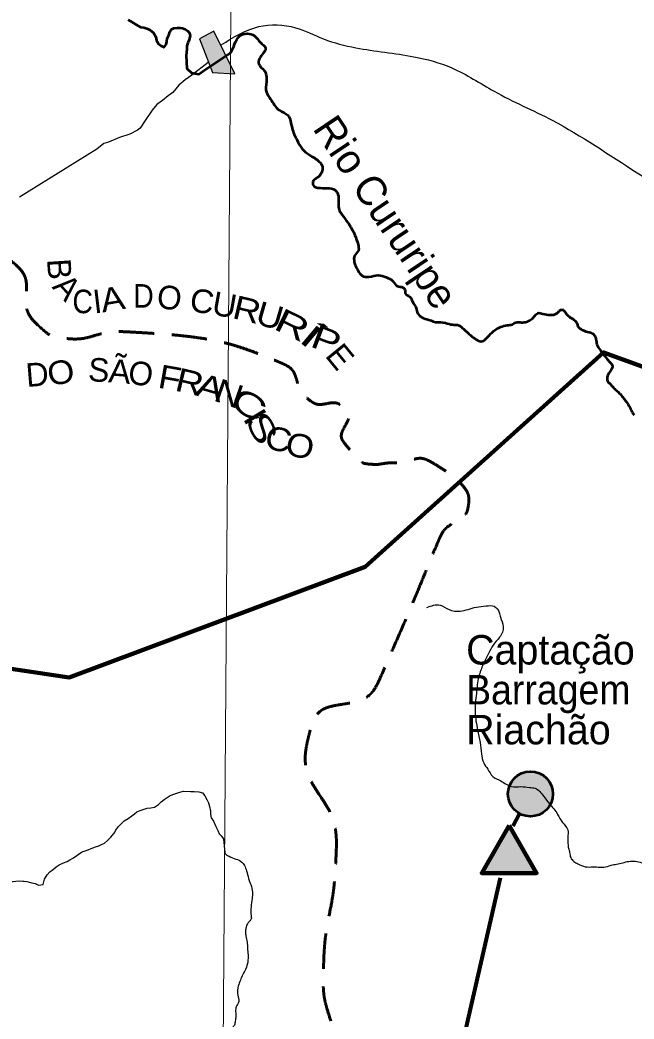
# Model space of a CAD drawing. Extents: x 553962 to 842807, y 8883888 to 9032388.
# Drawn here: x 770713 to 781131, y 8905842 to 8922804 of the extents above; entities that cross this region are included whole.
import ezdxf
from ezdxf.enums import TextEntityAlignment as Align

# ---------------------------------------------------------------- set-up
doc = ezdxf.new("R2010")
doc.units = 0
doc.header["$LTSCALE"] = 200
doc.linetypes.add('MEDIUM_DASHED', pattern=[4.5, 3, -1.5])
for name, color, linetype, lineweight in [('1', 7, 'Continuous', 13), ('10', 7, 'MEDIUM_DASHED', 60), ('12', 7, 'Continuous', 25), ('21', 7, 'Continuous', 25), ('24', 7, 'Continuous', 25), ('28', 7, 'Continuous', 40), ('41', 7, 'Continuous', 40), ('57', 7, 'Continuous', 13), ('9', 7, 'Continuous', 90)]:
    doc.layers.add(name, color=color, linetype=linetype, lineweight=lineweight)
doc.layers.add('49', color=7, linetype='Continuous')

msp = doc.modelspace()

# ---------------------------------------------------------------- hatches: boundary and pattern name
at = {"layer": '21'}
msp.add_hatch(color=256, dxfattribs=at).paths.add_polyline_path([(774002.3, 8922616.4), (773757.5, 8922483.3), (773979.6, 8921912.9), (774358.6, 8921888)])
at = {"layer": '28'}
for points in [[(779755.3, 8909663.4, 1), (778990.9, 8909663.4, 1)], [(779012.8, 8909126.4), (779478.9, 8908319.1), (778546.6, 8908319.1)]]:
    msp.add_hatch(color=256, dxfattribs=at).paths.add_polyline_path(points)

# ---------------------------------------------------------------- linework, layer by layer
at = {"layer": '1'}
msp.add_lwpolyline([(774987.1, 9020818), (774482.3, 8948876), (774053.6, 8890875.3)], dxfattribs=at)
at = {"layer": '10'}
msp.add_open_spline([(780116.2, 8904162.2), (779769.4, 8904177.9), (779422.6, 8904193.7), (779075.8, 8904209.5), (778695.9, 8904226.8), (778318.1, 8904159.8), (777941, 8904091.2), (777596, 8904028.4), (777262.1, 8903937.2), (776924.3, 8903854.6), (776803.3, 8903825.1), (776686.8, 8903750.4), (776569.7, 8903736.3), (776304.5, 8903704.6), (776099.5, 8903983.3), (775884, 8904233.1), (775776.3, 8904358), (775709.2, 8904488.3), (775694.9, 8904611.7), (775670.8, 8904818.6), (776050.4, 8904994.8), (776049.5, 8905226.7), (776047.7, 8905694.5), (775846.8, 8906171.8), (775860.4, 8906646.1), (775878.9, 8907296.2), (776043.6, 8907946.8), (776074.4, 8908597), (776108.2, 8909310.3), (775454.3, 8910013.8), (775625.2, 8910702.5), (775746.8, 8911192.8), (776625.7, 8911182.1), (776831, 8911648.8), (777030.2, 8912101.5), (777228.1, 8912557.1), (777420.7, 8913014.1), (777556.6, 8913336.6), (777687.6, 8913670.8), (777822.6, 8913984), (777919.6, 8914208.9), (778290.2, 8914361.2), (778319.1, 8914551.8), (778353.9, 8914781.3), (778054.2, 8915076.5), (777751.7, 8915261.5), (777515.3, 8915405.9), (777278.6, 8915289.1), (777042.4, 8915285.1), (776916.2, 8915283), (776790.1, 8915252.3), (776664.1, 8915261.5), (776484.7, 8915274.5), (776355.7, 8915449.8), (776238.5, 8915592.7), (776104.7, 8915755.7), (776352.4, 8916067), (776214.8, 8916207.7), (776079, 8916346.7), (775768.6, 8916238.7), (775623.8, 8916349.7), (775431, 8916497.3), (775387.1, 8916881.7), (775127.3, 8916988.4), (774292.1, 8917331.5), (773439.5, 8917458.1), (772578.9, 8917506.5), (772178.6, 8917529.1), (771773.4, 8917358), (771373.1, 8917411.9), (771257.5, 8917427.5), (771157.3, 8917493.9), (771065.7, 8917577.5), (770748.6, 8917866.7), (770887.1, 8918430.9), (770592.8, 8918689.4), (770430.6, 8918831.9), (770160.1, 8918847), (770001.8, 8918996.9), (769746.9, 8919238.3), (769557.2, 8919552.6), (769292.5, 8919801.2), (768866.2, 8920201.6), (768426.7, 8920562), (767897.5, 8920818.5), (767600.3, 8920962.5), (767240, 8920922), (766928.1, 8920842.2), (766588, 8920755), (766267.8, 8920606.4), (765982.4, 8920369), (765805, 8920221.5), (765830.9, 8919932), (765651.4, 8919801.2), (765249.7, 8919508.7), (764806.4, 8919315.8), (764351, 8919115.2), (764017, 8918968.1), (763624.4, 8918749.5), (763310.7, 8918831.3)], degree=3, dxfattribs=at)
at = {"layer": '12'}
msp.add_lwpolyline([(773904.7, 8922082.2), (773628.7, 8921864.1), (773516.4, 8921787.9), (773409.1, 8921696.4), (773306.7, 8921574.4), (773225, 8921513.4), (773133, 8921437.1), (773036, 8921371.1), (772954.1, 8921274.5), (772836.3, 8921096.4), (772754.3, 8920969.2), (772708.3, 8920933.6), (772575.6, 8920867.6), (772402.2, 8920806.8), (772213.4, 8920730.8), (772136.9, 8920705.4), (772014.3, 8920608.9), (770702.1, 8919796.2)], dxfattribs=at)
msp.add_spline([(774127.4, 8922381.7), (774762.8, 8922691.1), (775387.8, 8922672.2), (775861.3, 8922482.8), (776410.6, 8922331.3), (777395.4, 8922179.8), (778039.4, 8921990.4), (778759.1, 8921592.6), (779744, 8921100.2), (781183.4, 8920210), (782566, 8919452.4), (782831.5, 8919338.8)], degree=3, dxfattribs=at)
at = {"layer": '21'}
msp.add_lwpolyline([(774002.3, 8922616.4), (773757.5, 8922483.3), (773979.6, 8921912.9), (774358.6, 8921888)], close=True, dxfattribs=at)
at = {"layer": '24', "lineweight": 53}
msp.add_lwpolyline([(772547.5, 8922804), (772613.3, 8922767.9), (772689.3, 8922721.6), (772755.2, 8922680.4), (772816.2, 8922674.9), (772866.9, 8922659.3), (772917.6, 8922638.6), (772978.3, 8922587.3), (773018.5, 8922515.7), (773028.2, 8922454.6), (773063.5, 8922398.3), (773109, 8922362.3), (773159.7, 8922341.6), (773190.6, 8922387.3), (773206.2, 8922438.1), (773211.6, 8922489), (773235.3, 8922546.6), (773253.2, 8922600.3), (773278.8, 8922641.4), (773324.8, 8922663), (773387.4, 8922671.9), (773432.1, 8922671.9), (773467.8, 8922663), (773512.6, 8922645.1), (773557.3, 8922618.2), (773584.1, 8922591.4), (773593, 8922555.6), (773598.5, 8922537.5), (773582.7, 8922466.3), (773562, 8922415.5), (773541.3, 8922364.7), (773541, 8922313.7), (773535.5, 8922252.6), (773530.1, 8922201.7), (773543.8, 8921982.6), (773624.7, 8921905.7), (773745.1, 8921884.1), (773825.5, 8921937.8), (774289.1, 8922253.7)], dxfattribs=at)
at = {"layer": '24'}
for points in [[(771104.7, 8908124.9), (771111.7, 8908148.9), (771127.4, 8908215), (771173.7, 8908291.1), (771219.8, 8908341.8), (771281.2, 8908387.2), (771327.2, 8908427.7), (771378.3, 8908457.9), (771449.7, 8908493.1), (771511, 8908518.2), (771556.9, 8908543.4), (771618.2, 8908578.6), (771679.5, 8908619), (771720.4, 8908654.4), (771766.4, 8908679.6), (771868.3, 8908714.6), (771919.4, 8908739.7), (771995.8, 8908764.7), (772051.9, 8908784.7), (772097.8, 8908804.8), (772148.9, 8908829.9), (772195, 8908875.5), (772251.3, 8908931.1), (772307.7, 8908997), (772338.6, 8909047.7), (772379.6, 8909103.5), (772415.5, 8909144), (772482.1, 8909204.7), (772548.4, 8909245.1), (772609.8, 8909290.5), (772655.8, 8909325.9), (772696.7, 8909361.3), (772752.8, 8909381.3), (772803.8, 8909401.3), (772870.1, 8909421.3), (772931.2, 8909426), (772997.4, 8909440.8), (773063.8, 8909486.3), (773109.9, 8909526.7), (773161, 8909567.1), (773212.1, 8909602.5), (773263.2, 8909637.8), (773339.7, 8909667.9), (773426.3, 8909692.8), (773487.5, 8909707.7), (773604.5, 8909706.9), (773670.6, 8909706.5), (773746.8, 8909700.9), (773807.7, 8909680.2), (773848.1, 8909634), (773883.2, 8909567.6), (773908.3, 8909511.4), (773928.2, 8909450.2), (773942.9, 8909373.7), (773942.6, 8909317.6), (773957.4, 8909256.4), (773997.7, 8909200.1), (774032.7, 8909108.2), (774072.8, 8909031.5), (774092.9, 8908985.6), (774128.2, 8908949.7), (774163.5, 8908903.6), (774185.6, 8908665.7)], [(770408.6, 8908080.8), (770464.6, 8908100.9), (770526, 8908151.4), (770590.1, 8908175.8), (770641.1, 8908179.8), (770707.8, 8908187.6), (770758.8, 8908179.8), (770782.3, 8908183.7), (770829.4, 8908175.8), (770911.8, 8908152.3), (770970.6, 8908144.4), (771029.5, 8908116.9), (771104.7, 8908124.9)]]:
    msp.add_lwpolyline(points, dxfattribs=at)
at = {"layer": '24', "lineweight": 53}
for points in [[(774289.1, 8922253.7), (774354.7, 8922391.4), (774442, 8922536.8), (774689.1, 8922536.8), (774790.9, 8922420.5), (774878.1, 8922333.3), (774790.9, 8922173.4), (774761.8, 8922071.6), (774878.1, 8921911.7), (774892.6, 8921751.8), (774892.6, 8921577.3), (774965.3, 8921461), (775110.7, 8921272), (775256.1, 8921184.8), (775328.8, 8920966.7), (775414.3, 8920761.6), (775502.1, 8920615.2), (775624.1, 8920512.8), (775785.1, 8920400.6), (775843.6, 8920312.7), (775833.9, 8920220.1), (775750.9, 8920122.5), (775692.4, 8920078.6), (775692.4, 8919990.8), (775765.6, 8919956.6), (775921.7, 8919946.9), (776063.2, 8919912.7), (776097.3, 8919868.8), (776116.8, 8919751.7), (776126.6, 8919585.9), (776175.3, 8919502.9), (776272.9, 8919366.3), (776394.9, 8919151.7), (776448.5, 8918990.7), (776453.4, 8918888.2), (776390, 8918800.4), (776385.1, 8918698), (776409.5, 8918619.9), (776448.5, 8918546.8), (776512, 8918463.8), (776633.9, 8918444.3), (776790, 8918468.7), (776926.6, 8918434.6), (777043.7, 8918366.2), (777116.9, 8918283.3), (777209.6, 8918263.8), (777243.7, 8918224.8), (777248.6, 8918166.2), (777326.7, 8918104.2), (777375.5, 8918011.4), (777424.2, 8917938.2), (777453.5, 8917840.6), (777512, 8917767.4), (777614.5, 8917723.5), (777760.8, 8917674.7)], [(777760.8, 8917674.7), (777931.6, 8917660), (778053.6, 8917630.7), (778136.5, 8917625.8), (778238.9, 8917557.5), (778356, 8917450.1), (778453.6, 8917376.9), (778536.5, 8917347.6), (778609.7, 8917381.8), (778702.4, 8917479.4), (778790.2, 8917552.6), (778868.2, 8917591.7), (778980.5, 8917621), (779063.4, 8917635.6), (779126.8, 8917669.8), (779224.4, 8917669.8), (779307.3, 8917679.5), (779375.6, 8917713.7), (779439, 8917767.4), (779497.6, 8917826), (779585.4, 8917816.2), (779702.5, 8917796.7), (779756.1, 8917796.7), (779843.9, 8917845.5), (779883, 8917879.7), (779931.7, 8917879.7), (779965.9, 8917835.7), (780029.3, 8917767.4), (780109.8, 8917713.7), (780163.5, 8917645.4), (780187.8, 8917586.8), (780236.6, 8917552.6), (780290.3, 8917523.3), (780392.7, 8917498.9), (780451.3, 8917459.9), (780485.4, 8917381.8), (780500.1, 8917293.9), (780548.8, 8917211), (780621.5, 8917109.9), (780695, 8917023.2), (780736.5, 8916974.2), (780766.6, 8916932.7), (780764.7, 8916906.3), (780717.6, 8916827.1), (780676.1, 8916734.8), (780679.9, 8916678.2), (780713.8, 8916634.8), (780774.2, 8916568.9), (780834.5, 8916512.3), (780885.4, 8916463.3), (780938.2, 8916401.1), (780996.6, 8916325.7), (781043.7, 8916254.1), (781083.3, 8916178.7), (781130.5, 8916097.6)]]:
    msp.add_spline(points, degree=3, dxfattribs=at)
at = {"layer": '24'}
for points in [[(777617.6, 8912828.3), (777839.2, 8912869.9), (777991.6, 8912793.7), (778178.6, 8912766), (778455.7, 8912835.2), (778621.9, 8912856), (778760.5, 8912849.1), (778843.6, 8912745.2), (778864.3, 8912662.1), (778912.8, 8912502.8), (778850.5, 8912322.7), (778739.7, 8912191.1), (778663.5, 8912045.6), (778573.4, 8911865.5), (778497.2, 8911657.7), (778455.7, 8911366.8), (778434.9, 8911048.2), (778476.5, 8910750.4), (778518, 8910535.6), (778545.7, 8910341.7), (778580.4, 8910189.3), (778649.6, 8910085.4), (778732.8, 8909960.8), (778871.3, 8909884.6), (779051.4, 8909787.6), (779210.7, 8909787.6), (779356.1, 8909773.7), (779453.1, 8909759.9), (779598.6, 8909621.3), (779695.5, 8909496.7), (779834.1, 8909316.6), (779917.2, 8909178.1), (780007.2, 8909053.4), (780007.2, 8908921.8), (780009.3, 8908822.2), (780018.8, 8908742.2), (780037.6, 8908666.9), (780056.4, 8908582.2), (780110.5, 8908518.7), (780178.7, 8908476.4), (780303.4, 8908427), (780439.8, 8908424.6), (780552.7, 8908419.9), (780618.6, 8908419.9), (780740.9, 8908452.8), (780832.7, 8908471.7), (780938.5, 8908495.2), (781042, 8908518.7), (781150.2, 8908521.1), (781263.2, 8908495.2), (781387.8, 8908429.3), (781472.5, 8908377.6), (781569, 8908323.5), (781672.5, 8908252.9), (781759.5, 8908175.3)], [(774185.6, 8908665.7), (774206.6, 8908640.3), (774262.2, 8908604.4), (774377, 8908558), (774477.9, 8908507), (774520.8, 8908450.2), (774556.7, 8908357.5), (774590.3, 8908228.8), (774637.8, 8908089.7), (774657, 8907966.8), (774646.5, 8907852.1), (774629.1, 8907712.9), (774632.6, 8907601.7), (774636.1, 8907542.5), (774608.3, 8907500.8), (774570, 8907459.1), (774545.7, 8907382.6), (774537.9, 8907322.4), (774546.2, 8907252.2), (774566.8, 8907147.9), (774572, 8907048.8), (774582.3, 8906929.1), (774580.2, 8906846.2), (774553.4, 8906721.3), (774483.2, 8906572.6), (774441.9, 8906478.6), (774411, 8906374.3), (774403.7, 8906304.8), (774420.2, 8906190.2), (774426.4, 8906138.5), (774400.6, 8906085.9), (774376.9, 8906034.2), (774372.8, 8905948.5), (774375.9, 8905877.3), (774365.5, 8905808.1), (774350, 8905739.9), (774314.9, 8905694.5), (774270.6, 8905633.5), (774243.7, 8905593.3), (774221, 8905553), (774216.9, 8905506.5), (774205.5, 8905472.4), (774207.6, 8905414.6), (774213.8, 8905325.8), (774211.7, 8905257.6), (774247.8, 8905209.1), (774287.1, 8905162.6), (774350, 8905098.6), (774387.2, 8905056.3), (774415, 8904970.4), (774420.2, 8904906.4), (774418.1, 8904863), (774400.6, 8904807.3), (774394.4, 8904756.7), (774392.3, 8904706.1)]]:
    msp.add_spline(points, degree=3, dxfattribs=at)
at = {"layer": '28', "lineweight": 80}
for p, q in [((779080.3, 8909120.8), (779191.5, 8909337.8)), ((778032.3, 8904595.6), (778867.6, 8908237.2))]:
    msp.add_line(p, q, dxfattribs=at)
at = {"layer": '28', "lineweight": 90}
msp.add_lwpolyline([(779012.8, 8909126.4), (779478.9, 8908319.1), (778546.6, 8908319.1)], close=True, dxfattribs=at)
at = {"layer": '28', "lineweight": 53}
msp.add_circle((779373.1, 8909663.4), 382.2, dxfattribs=at)
at = {"layer": '57', "lineweight": 25}
msp.add_lwpolyline([(765974.5, 8912469.6), (771548.8, 8911642.3), (776566.8, 8913518.4), (780614.1, 8917160.1), (782189.6, 8916587.3), (785656.2, 8919415.9), (791912, 8922868)], dxfattribs=at)
at = {"layer": '57', "lineweight": 90}
msp.add_lwpolyline([(765974.5, 8912469.6), (771548.8, 8911642.3), (776566.8, 8913518.4), (780614.1, 8917160.1), (782189.6, 8916587.3), (785656.2, 8919415.9), (791912, 8922868)], dxfattribs=at)
at = {"layer": '9'}
msp.add_lwpolyline([(765974.5, 8912469.6), (771548.8, 8911642.3), (776566.8, 8913518.4), (780614.1, 8917160.1), (782189.6, 8916587.3), (785656.2, 8919415.9), (791912, 8922868)], dxfattribs=at)

# ---------------------------------------------------------------- texts
at = {"layer": '10'}
for s, rotation, p in [('B', 273.7, (771182.6, 8918561.9)), ('A', 312.27, (771365.1, 8918132.2)), ('O', 355.328, (773232.9, 8917891.1)), ('I', 6.726, (772047.4, 8917827.9)), ('E', 309.301, (775989.3, 8916961)), ('D', 4.609, (771020.3, 8916587.2)), ('S', 356.776, (772039.9, 8916663.1)), ('O', 353.119, (772739.5, 8916603.3))]:
    msp.add_text(s, height=400, rotation=rotation, dxfattribs=at).set_placement(p, align=Align.CENTER)
for s, rotation, width, p in [('D', 0.236, 0.9, (772808.5, 8917919.6)), ('C', 359.4, 0.9, (771774.6, 8917825.1)), ('A', 9.637, 1.15, (772314.8, 8917870.3)), ('C', 352.107, 1.05, (773776, 8917831)), ('U', 349.875, 1.05, (774148.5, 8917770.9)), ('R', 346.703, 1.2, (774520.9, 8917691.9)), ('U', 343.896, 1.15, (774897.3, 8917591.2)), ('R', 334.15, 1.45, (775247.1, 8917444.1)), ('Í', 319.844, 1.7, (775521.5, 8917280.7)), ('P', 339.291, 1.35, (775841.5, 8917181.7)), ('Ã', 355.328, 1.05, (772390.6, 8916638.8)), ('O', 9.637, 1.1, (771438, 8916625.6)), ('F', 349.875, 1.15, (773220.9, 8916530.8)), ('R', 346.703, 1.2, (773547.6, 8916462.3)), ('A', 343.896, 1.3, (773886.4, 8916372.5)), ('N', 340.873, 1.2, (774194.5, 8916271.5)), ('C', 328.723, 1.55, (774493, 8916104)), ('I', 301.588, 1.25, (774530.3, 8915964.2)), ('S', 297.643, 1.5, (774641.5, 8915785)), ('C', 347.533, 1.15, (775056.3, 8915491.9)), ('O', 347.535, 1.15, (775421.7, 8915378.7))]:
    msp.add_text(s, height=400, rotation=rotation, dxfattribs=dict(at, width=width)).set_placement(p, align=Align.CENTER)
at = {"layer": '41'}
for s, p in [('Captação', (778282, 8911861)), ('Riachão', (778282, 8910505.2))]:
    msp.add_text(s, height=500, dxfattribs=at).set_placement(p)
at = {"layer": '41', "width": 0.95}
msp.add_text('Barragem', height=500, dxfattribs=at).set_placement((778282, 8911183.1))
at = {"layer": '49'}
msp.add_text('Rio Cururipe', height=500, rotation=303.874, dxfattribs=at).set_placement((776713.2, 8919402.4), align=Align.CENTER)

doc.saveas('drawing.dxf')
